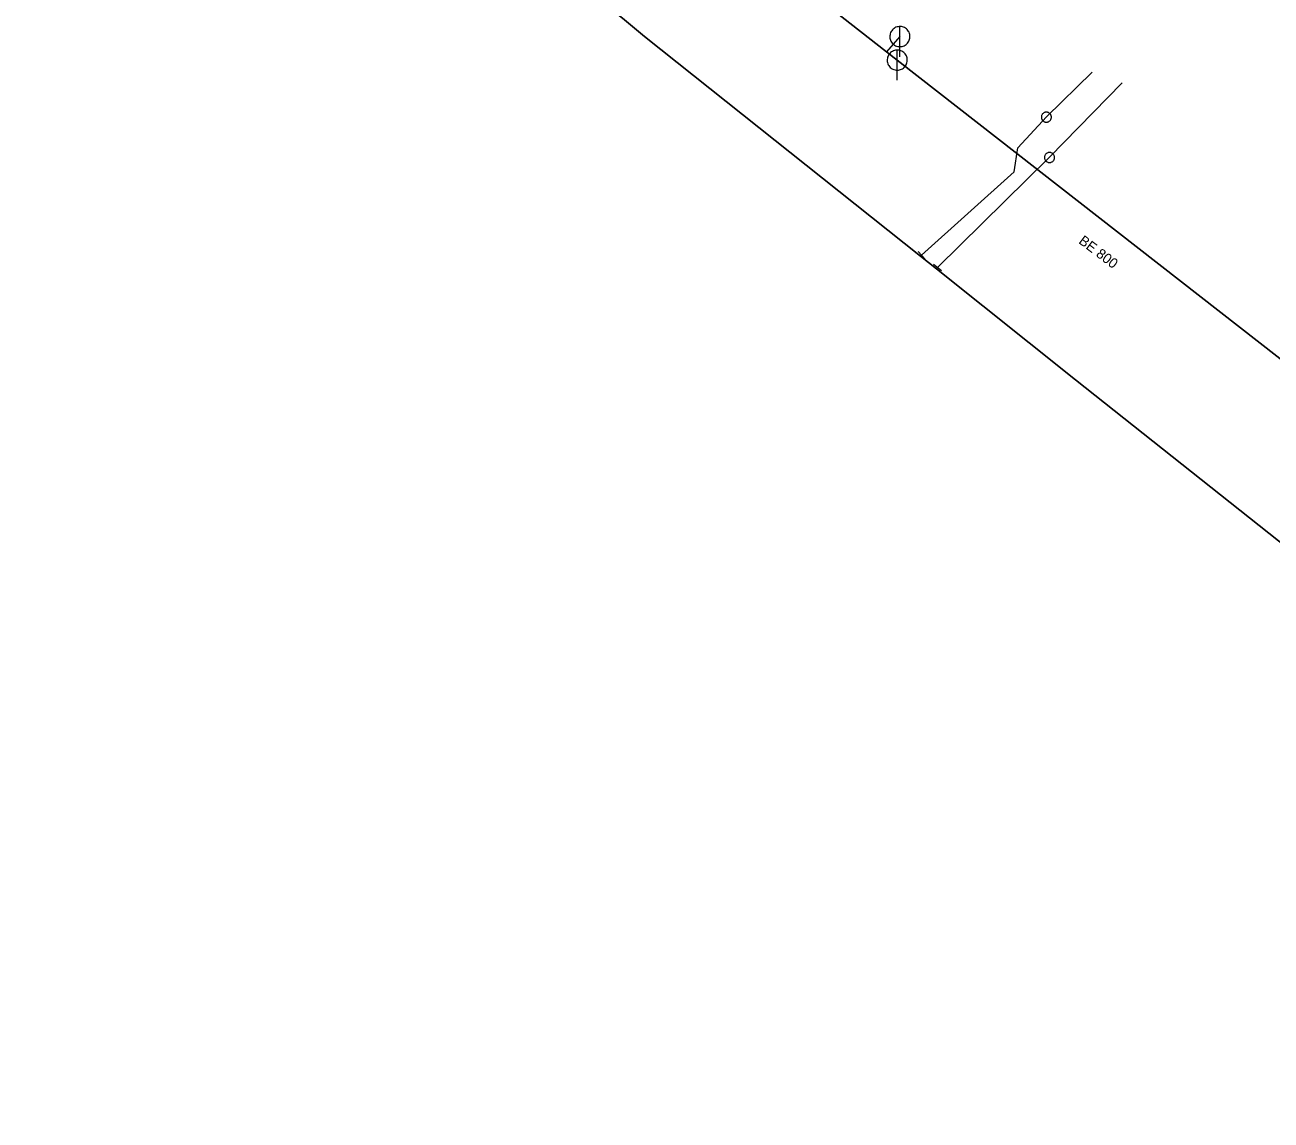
# Model space of a CAD drawing. Extents: x -807203 to -805207, y -993656 to -992505.
# Drawn here: x -806260.1 to -806136.1, y -993223.1 to -993114.2 of the extents above; entities that cross this region are included whole.
import ezdxf

# ---------------------------------------------------------------- set-up
doc = ezdxf.new("R2010")
doc.units = 0
doc.header["$LTSCALE"] = 0.4
for name, color, linetype, lineweight in [('1', 7, 'Continuous', 13), ('11', 7, 'Continuous', 13), ('13', 7, 'Continuous', 13), ('14', 7, 'Continuous', 25), ('17', 7, 'Continuous', 25), ('22', 7, 'Continuous', 13), ('23', 7, 'Continuous', 13), ('34', 7, 'Continuous', 13)]:
    doc.layers.add(name, color=color, linetype=linetype, lineweight=lineweight)

msp = doc.modelspace()

# ---------------------------------------------------------------- linework, layer by layer
at = {"layer": '11'}
msp.add_line((-806173.039, -993115.328), (-806174.365, -993116.849), dxfattribs=at)
at = {"layer": '13'}
for p, q in [((-806158.472, -993123.305), (-806153.918, -993118.874)), ((-806158.156, -993127.318), (-806150.93, -993119.914)), ((-806169.307, -993138.279), (-806158.156, -993127.318))]:
    msp.add_line(p, q, dxfattribs=at)
msp.add_lwpolyline([(-806170.883, -993137.057), (-806161.672, -993128.782), (-806161.303, -993126.382), (-806158.472, -993123.305)], dxfattribs=at)
at = {"layer": '14'}
msp.add_line((-806173.301, -993117.667), (-806128.75, -993152.399), dxfattribs=at)
at = {"layer": '14', "lineweight": 13}
for p, q in [((-806170.996, -993137.161), (-806170.883, -993137.057)), ((-806169.414, -993138.403), (-806169.307, -993138.279))]:
    msp.add_line(p, q, dxfattribs=at)
at = {"layer": '14'}
msp.add_lwpolyline([(-806213.75, -993086.03), (-806174.365, -993116.849), (-806173.301, -993117.667)], dxfattribs=at)
at = {"layer": '17'}
msp.add_lwpolyline([(-806260.066, -993064.828), (-806248.392, -993074.528), (-806229.53, -993089.861), (-806208.251, -993107.276), (-806200.433, -993113.675), (-806198.425, -993115.318), (-806170.996, -993137.161), (-806169.414, -993138.403), (-806155.574, -993149.442), (-806086.497, -993204.202), (-806063.424, -993223.055)], dxfattribs=at)
at = {"layer": '22'}
for p, q in [((-806173.039, -993117.328), (-806173.038, -993114.328)), ((-806173.301, -993119.667), (-806173.3, -993116.667))]:
    msp.add_line(p, q, dxfattribs=at)
for points in [[(-806172.039, -993115.328), (-806172.044, -993115.219), (-806172.062, -993115.111), (-806172.092, -993115.005), (-806172.132, -993114.904), (-806172.184, -993114.807), (-806172.246, -993114.717), (-806172.318, -993114.634), (-806172.398, -993114.56), (-806172.486, -993114.494), (-806172.58, -993114.439), (-806172.68, -993114.394), (-806172.785, -993114.361), (-806172.892, -993114.339), (-806173.001, -993114.329), (-806173.111, -993114.331), (-806173.219, -993114.345), (-806173.326, -993114.37), (-806173.429, -993114.407), (-806173.527, -993114.456), (-806173.619, -993114.514), (-806173.705, -993114.583), (-806173.782, -993114.66), (-806173.851, -993114.746), (-806173.91, -993114.838), (-806173.958, -993114.936), (-806173.995, -993115.039), (-806174.021, -993115.146), (-806174.035, -993115.254), (-806174.038, -993115.364), (-806174.028, -993115.473), (-806174.007, -993115.58), (-806173.973, -993115.684), (-806173.929, -993115.784), (-806173.874, -993115.879), (-806173.808, -993115.967), (-806173.734, -993116.047), (-806173.651, -993116.119), (-806173.561, -993116.181), (-806173.465, -993116.233), (-806173.363, -993116.274), (-806173.258, -993116.304), (-806173.15, -993116.322), (-806173.04, -993116.328), (-806172.931, -993116.322), (-806172.823, -993116.304), (-806172.718, -993116.275), (-806172.616, -993116.234), (-806172.519, -993116.182), (-806172.429, -993116.12), (-806172.346, -993116.049), (-806172.271, -993115.969), (-806172.206, -993115.881), (-806172.15, -993115.787), (-806172.106, -993115.687), (-806172.072, -993115.583), (-806172.05, -993115.475), (-806172.04, -993115.366)], [(-806172.301, -993117.667), (-806172.306, -993117.558), (-806172.324, -993117.45), (-806172.354, -993117.344), (-806172.394, -993117.243), (-806172.446, -993117.146), (-806172.508, -993117.056), (-806172.58, -993116.973), (-806172.66, -993116.899), (-806172.748, -993116.833), (-806172.842, -993116.778), (-806172.942, -993116.733), (-806173.047, -993116.7), (-806173.154, -993116.678), (-806173.263, -993116.668), (-806173.373, -993116.67), (-806173.481, -993116.684), (-806173.588, -993116.709), (-806173.691, -993116.746), (-806173.789, -993116.795), (-806173.881, -993116.853), (-806173.967, -993116.922), (-806174.044, -993116.999), (-806174.113, -993117.085), (-806174.172, -993117.177), (-806174.22, -993117.275), (-806174.257, -993117.378), (-806174.283, -993117.485), (-806174.297, -993117.593), (-806174.3, -993117.703), (-806174.29, -993117.812), (-806174.269, -993117.919), (-806174.235, -993118.023), (-806174.191, -993118.123), (-806174.136, -993118.218), (-806174.07, -993118.306), (-806173.996, -993118.386), (-806173.913, -993118.458), (-806173.823, -993118.52), (-806173.727, -993118.572), (-806173.625, -993118.613), (-806173.52, -993118.643), (-806173.412, -993118.661), (-806173.302, -993118.667), (-806173.193, -993118.661), (-806173.085, -993118.643), (-806172.98, -993118.614), (-806172.878, -993118.573), (-806172.781, -993118.521), (-806172.691, -993118.459), (-806172.608, -993118.388), (-806172.533, -993118.308), (-806172.468, -993118.22), (-806172.412, -993118.126), (-806172.368, -993118.026), (-806172.334, -993117.922), (-806172.312, -993117.814), (-806172.302, -993117.705)]]:
    msp.add_lwpolyline(points, close=True, dxfattribs=at)
at = {"layer": '23'}
for points in [[(-806158.136, -993122.965), (-806158.177, -993122.932), (-806158.221, -993122.903), (-806158.267, -993122.881), (-806158.316, -993122.862), (-806158.366, -993122.848), (-806158.419, -993122.841), (-806158.471, -993122.838), (-806158.522, -993122.841), (-806158.574, -993122.848), (-806158.625, -993122.862), (-806158.674, -993122.88), (-806158.721, -993122.905), (-806158.765, -993122.933), (-806158.804, -993122.966), (-806158.842, -993123.002), (-806158.875, -993123.044), (-806158.903, -993123.086), (-806158.928, -993123.135), (-806158.946, -993123.182), (-806158.96, -993123.233), (-806158.967, -993123.286), (-806158.97, -993123.338), (-806158.967, -993123.391), (-806158.96, -993123.442), (-806158.946, -993123.492), (-806158.926, -993123.541), (-806158.903, -993123.587), (-806158.874, -993123.631), (-806158.841, -993123.671), (-806158.805, -993123.709), (-806158.764, -993123.742), (-806158.72, -993123.77), (-806158.673, -993123.794), (-806158.625, -993123.813), (-806158.575, -993123.825), (-806158.523, -993123.834), (-806158.47, -993123.837), (-806158.417, -993123.834), (-806158.366, -993123.826)], [(-806158.928, -993123.135), (-806158.946, -993123.182), (-806158.96, -993123.233), (-806158.967, -993123.286), (-806158.97, -993123.338), (-806158.967, -993123.391), (-806158.96, -993123.442), (-806158.946, -993123.492), (-806158.926, -993123.541), (-806158.903, -993123.587), (-806158.874, -993123.631), (-806158.841, -993123.671), (-806158.805, -993123.709), (-806158.764, -993123.742), (-806158.72, -993123.77), (-806158.673, -993123.794), (-806158.625, -993123.813), (-806158.575, -993123.825), (-806158.523, -993123.834), (-806158.47, -993123.837), (-806158.417, -993123.834), (-806158.366, -993123.826), (-806158.316, -993123.813), (-806158.267, -993123.793), (-806158.22, -993123.771), (-806158.176, -993123.741), (-806158.137, -993123.708), (-806158.099, -993123.672), (-806158.067, -993123.631), (-806158.038, -993123.587), (-806158.013, -993123.54), (-806157.996, -993123.491), (-806157.981, -993123.44), (-806157.973, -993123.39), (-806157.972, -993123.336), (-806157.973, -993123.285), (-806157.982, -993123.233), (-806157.995, -993123.182), (-806158.014, -993123.133), (-806158.038, -993123.087)], [(-806158.366, -993123.826), (-806158.316, -993123.813), (-806158.267, -993123.793), (-806158.22, -993123.771), (-806158.176, -993123.741), (-806158.137, -993123.708), (-806158.099, -993123.672), (-806158.067, -993123.631), (-806158.038, -993123.587), (-806158.013, -993123.54), (-806157.996, -993123.491), (-806157.981, -993123.44), (-806157.973, -993123.39), (-806157.972, -993123.336), (-806157.973, -993123.285), (-806157.982, -993123.233), (-806157.995, -993123.182), (-806158.014, -993123.133), (-806158.038, -993123.087), (-806158.067, -993123.043), (-806158.099, -993123.003), (-806158.136, -993122.965), (-806158.177, -993122.932), (-806158.221, -993122.903), (-806158.267, -993122.881), (-806158.316, -993122.862), (-806158.366, -993122.848), (-806158.419, -993122.841), (-806158.471, -993122.838), (-806158.522, -993122.841), (-806158.574, -993122.848), (-806158.625, -993122.862), (-806158.674, -993122.88), (-806158.721, -993122.905), (-806158.765, -993122.933), (-806158.804, -993122.966), (-806158.842, -993123.002), (-806158.875, -993123.044), (-806158.903, -993123.086), (-806158.928, -993123.135)], [(-806158.038, -993123.087), (-806158.067, -993123.043), (-806158.099, -993123.003), (-806158.136, -993122.965)], [(-806157.802, -993126.996), (-806157.842, -993126.961), (-806157.884, -993126.93), (-806157.929, -993126.905), (-806157.977, -993126.883), (-806158.027, -993126.867), (-806158.079, -993126.857), (-806158.13, -993126.851), (-806158.182, -993126.852), (-806158.234, -993126.857), (-806158.285, -993126.867), (-806158.336, -993126.883), (-806158.384, -993126.905), (-806158.429, -993126.931), (-806158.47, -993126.962), (-806158.509, -993126.996), (-806158.545, -993127.036), (-806158.575, -993127.077), (-806158.602, -993127.124), (-806158.623, -993127.17), (-806158.64, -993127.22), (-806158.65, -993127.273), (-806158.655, -993127.324), (-806158.655, -993127.377), (-806158.651, -993127.429), (-806158.639, -993127.479), (-806158.622, -993127.53), (-806158.601, -993127.577), (-806158.575, -993127.622), (-806158.544, -993127.664), (-806158.509, -993127.704), (-806158.471, -993127.739), (-806158.428, -993127.77), (-806158.382, -993127.796), (-806158.335, -993127.817), (-806158.286, -993127.832), (-806158.234, -993127.843), (-806158.182, -993127.849), (-806158.129, -993127.849), (-806158.077, -993127.843)], [(-806158.602, -993127.124), (-806158.623, -993127.17), (-806158.64, -993127.22), (-806158.65, -993127.273), (-806158.655, -993127.324), (-806158.655, -993127.377), (-806158.651, -993127.429), (-806158.639, -993127.479), (-806158.622, -993127.53), (-806158.601, -993127.577), (-806158.575, -993127.622), (-806158.544, -993127.664), (-806158.509, -993127.704), (-806158.471, -993127.739), (-806158.428, -993127.77), (-806158.382, -993127.796), (-806158.335, -993127.817), (-806158.286, -993127.832), (-806158.234, -993127.843), (-806158.182, -993127.849), (-806158.129, -993127.849), (-806158.077, -993127.843), (-806158.027, -993127.833), (-806157.977, -993127.816), (-806157.929, -993127.796), (-806157.884, -993127.768), (-806157.842, -993127.738), (-806157.803, -993127.704), (-806157.769, -993127.664), (-806157.737, -993127.622), (-806157.71, -993127.577), (-806157.69, -993127.529), (-806157.673, -993127.479), (-806157.662, -993127.429), (-806157.658, -993127.376), (-806157.657, -993127.324), (-806157.662, -993127.272), (-806157.673, -993127.22), (-806157.69, -993127.17), (-806157.711, -993127.123)], [(-806158.077, -993127.843), (-806158.027, -993127.833), (-806157.977, -993127.816), (-806157.929, -993127.796), (-806157.884, -993127.768), (-806157.842, -993127.738), (-806157.803, -993127.704), (-806157.769, -993127.664), (-806157.737, -993127.622), (-806157.71, -993127.577), (-806157.69, -993127.529), (-806157.673, -993127.479), (-806157.662, -993127.429), (-806157.658, -993127.376), (-806157.657, -993127.324), (-806157.662, -993127.272), (-806157.673, -993127.22), (-806157.69, -993127.17), (-806157.711, -993127.123), (-806157.738, -993127.078), (-806157.768, -993127.036), (-806157.802, -993126.996), (-806157.842, -993126.961), (-806157.884, -993126.93), (-806157.929, -993126.905), (-806157.977, -993126.883), (-806158.027, -993126.867), (-806158.079, -993126.857), (-806158.13, -993126.851), (-806158.182, -993126.852), (-806158.234, -993126.857), (-806158.285, -993126.867), (-806158.336, -993126.883), (-806158.384, -993126.905), (-806158.429, -993126.931), (-806158.47, -993126.962), (-806158.509, -993126.996), (-806158.545, -993127.036), (-806158.575, -993127.077), (-806158.602, -993127.124)], [(-806157.711, -993127.123), (-806157.738, -993127.078), (-806157.768, -993127.036), (-806157.802, -993126.996)]]:
    msp.add_lwpolyline(points, dxfattribs=at)
at = {"layer": '34'}
for p, q in [((-806171.222, -993136.689), (-806170.544, -993137.424)), ((-806169.697, -993137.967), (-806168.916, -993138.591))]:
    msp.add_line(p, q, dxfattribs=at)

# ---------------------------------------------------------------- texts
at = {"layer": '1'}
msp.add_text('BE 800', height=1, rotation=323, dxfattribs=at).set_placement((-806155.333, -993135.815))

doc.saveas('drawing.dxf')
